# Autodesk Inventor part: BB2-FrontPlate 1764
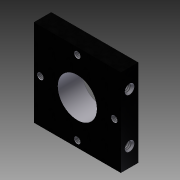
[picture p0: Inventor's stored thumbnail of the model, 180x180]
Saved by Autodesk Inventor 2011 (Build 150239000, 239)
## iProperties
Company: FirstCadLibrary
Shininess: 64.0
Length Units: 11269
Angle Units: 11279
Time Units: 11290
Mass Units: 11283
Length Display Precision: 3
Angle Display Precision: 2
Compacted: True
Part Number: BB2-FrontPlate 1764
Document SubType Name: Modeling
Created: 2007-01
Designer: Ed Sparks
Material: Aluminum-6061-AHC
Catalog Web Link: www.banebots.com
Vendor: BaneBots
Mass: 132.736 g
Surface Area: 141.952 cm^2
Volume: 48.98 cm^3
Density: 2.71 g/cm^3
Density: 0.0
Volumn: 0.0
Area: 0.0
PropertySet Name: Model Information
Control State: 0
Master: False
Checked Out: False
Author: Ed Sparks
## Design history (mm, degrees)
sketch "Sketch1"
  geometry: L1 (-31.75, 31.75)-(31.75, 31.75); L2 (31.75, 31.75)-(31.75, -31.75); L3 (31.75, -31.75)-(-31.75, -31.75); L4 (-31.75, -31.75)-(-31.75, 31.75); L5 (0, 0)-(0, 31.75); L6 (0, 0)-(0, -31.75); L7 (0, 0)-(31.75, 0); L8 (0, 0)-(-31.75, 0)
  constraints: 16 end point, 4 midpoint, 2 collinear, 2 parallel, 1 horizontal, 1 perpendicular, 1 other
  dimensions: "d0" = 63.5 distance of L1.end L2.end; "d1" = 63.5 distance of L1.start L1.end
extrude "Extrusion1" new body sketch "Sketch1" stored distance "d2" = 12.7; taper "d3" = 0 deg
sketch "Sketch6"
  geometry: C1 r 25 at (0, 0)
  constraints: 1 centre point
  dimensions: "d13" = 50 diameter of C1
extrude "Extrusion4" join sketch "Sketch6" distance "d14" = 6; taper "d15" = 0 deg
sketch "Sketch8"
  geometry: C1 r 25 at (0, 0) reference; 1 further point
  constraints: 1 coincident
hole "Hole2" sketch "Sketch8" at (0, 0) diameter "d28" = 28.575; stored, may be unused: countersink angle "d32" = 82 deg, drill point angle "d34" = 118 deg; dims "d29" = 6, "d30" = 6.3, "d31" = 10.3, "d33" = 8
chamfer "Chamfer1" distance "d35" = 1; stored, may be unused: second distance "d36" = 2, angle "d72" = 45 deg
sketch "Sketch9"
  geometry: L1 (63.5, 0)-(0, 0) reference; L2 (0, 0)-(0, -12.7) reference; L3 (0, -12.7)-(63.5, -12.7) reference; L4 (63.5, 0)-(63.5, -12.7) reference; L5 (0, -6.35)-(63.5, -6.35); L6 (31.75, 0)-(31.75, -12.7); 1 further point
  constraints: 4 end point, 4 midpoint, 1 point on line
  dimensions: "d37" = 18 distance from line of point (13.75, -6.35) L6
hole "Hole3" sketch "Sketch9" at (13.75, -6.35) diameter "d38" = 4.978; stored, may be unused: countersink angle "d42" = 82 deg, drill point angle "d44" = 118 deg; dims "d39" = 12, "d40" = 6.3, "d41" = 10.3, "d43" = 13.7
mirror "Mirror1"
mirror "Mirror2"
chamfer "Chamfer2" distance "d45" = 1; stored, may be unused: second distance "d46" = 2, angle "d73" = 45 deg
workplane "Work Plane1"
sketch "Sketch10"
  geometry: L1 (-31.75, -6.35)-(31.75, -6.35) reference; L2 (0, -6.35)-(0, -22.916); 1 further point
  constraints: 2 end point, 1 midpoint, 1 perpendicular, 1 point on line
  dimensions: "d48" = 3.5 distance from line of point (0, -9.85) L1
hole "Hole4" sketch "Sketch10" at (0, -9.85) diameter "d49" = 2.459; stored, may be unused: countersink angle "d53" = 82 deg, drill point angle "d55" = 118 deg; dims "d50" = 6, "d51" = 6.3, "d52" = 10.3, "d54" = 7.5
pattern_circular "Circular Pattern2" dims angle "d58" = 360 deg
sketch "Sketch11"
  geometry: L1 (31.75, -31.75)-(-31.75, -31.75) reference; L2 (0, 0)-(36.641, 0); C1 r 14.287 at (0, 0) reference; 1 further point
  constraints: 2 end point, 1 parallel, 1 point on line
  dimensions: "d59" = 26.9875 distance of point (26.988, 0) L2.start
hole "Hole5" sketch "Sketch11" at (26.988, 0) diameter "d60" = 4.134; stored, may be unused: countersink angle "d64" = 82 deg, drill point angle "d66" = 118 deg; dims "d61" = 6, "d62" = 4, "d63" = 2, "d65" = 8
pattern_circular "Circular Pattern3" dims angle "d69" = 360 deg
chamfer "Chamfer3" distance "d70" = 0.25; stored, may be unused: second distance "d71" = 2, angle "d74" = 45 deg
body "Solid1"
other parameters: "d47" = 25
